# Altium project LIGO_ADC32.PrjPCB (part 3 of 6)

## Sheet FPGA_ARTIX7.SchDoc: FPGA
size C; Organization: Altium Limited; Address1: L3, 12a Rodborough Rd; Address2: Frenchs Forest; Address3: NSW; Address4: Australia 2086; DocumentNumber: 7; SheetNumber: 15; SheetTotal: 17
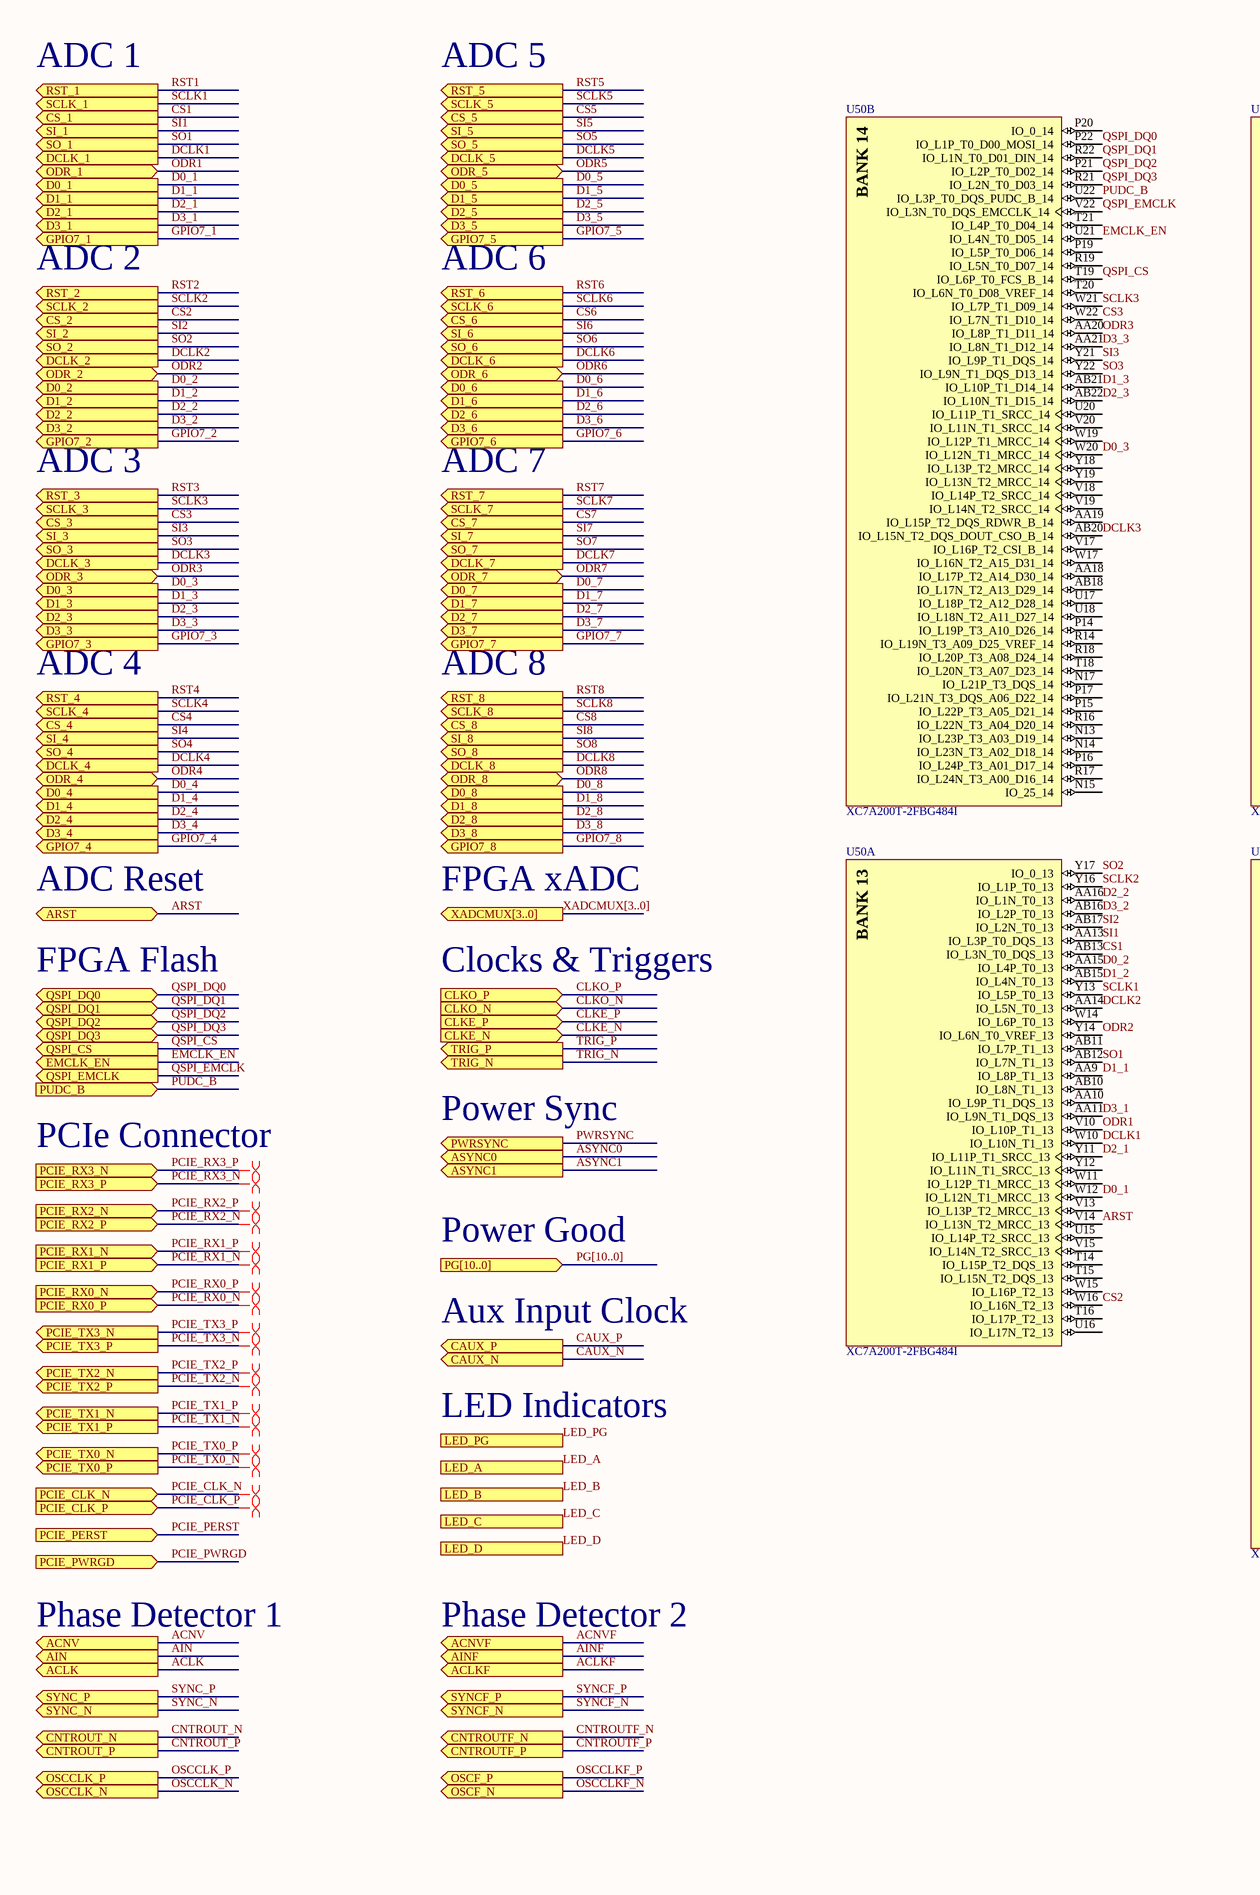
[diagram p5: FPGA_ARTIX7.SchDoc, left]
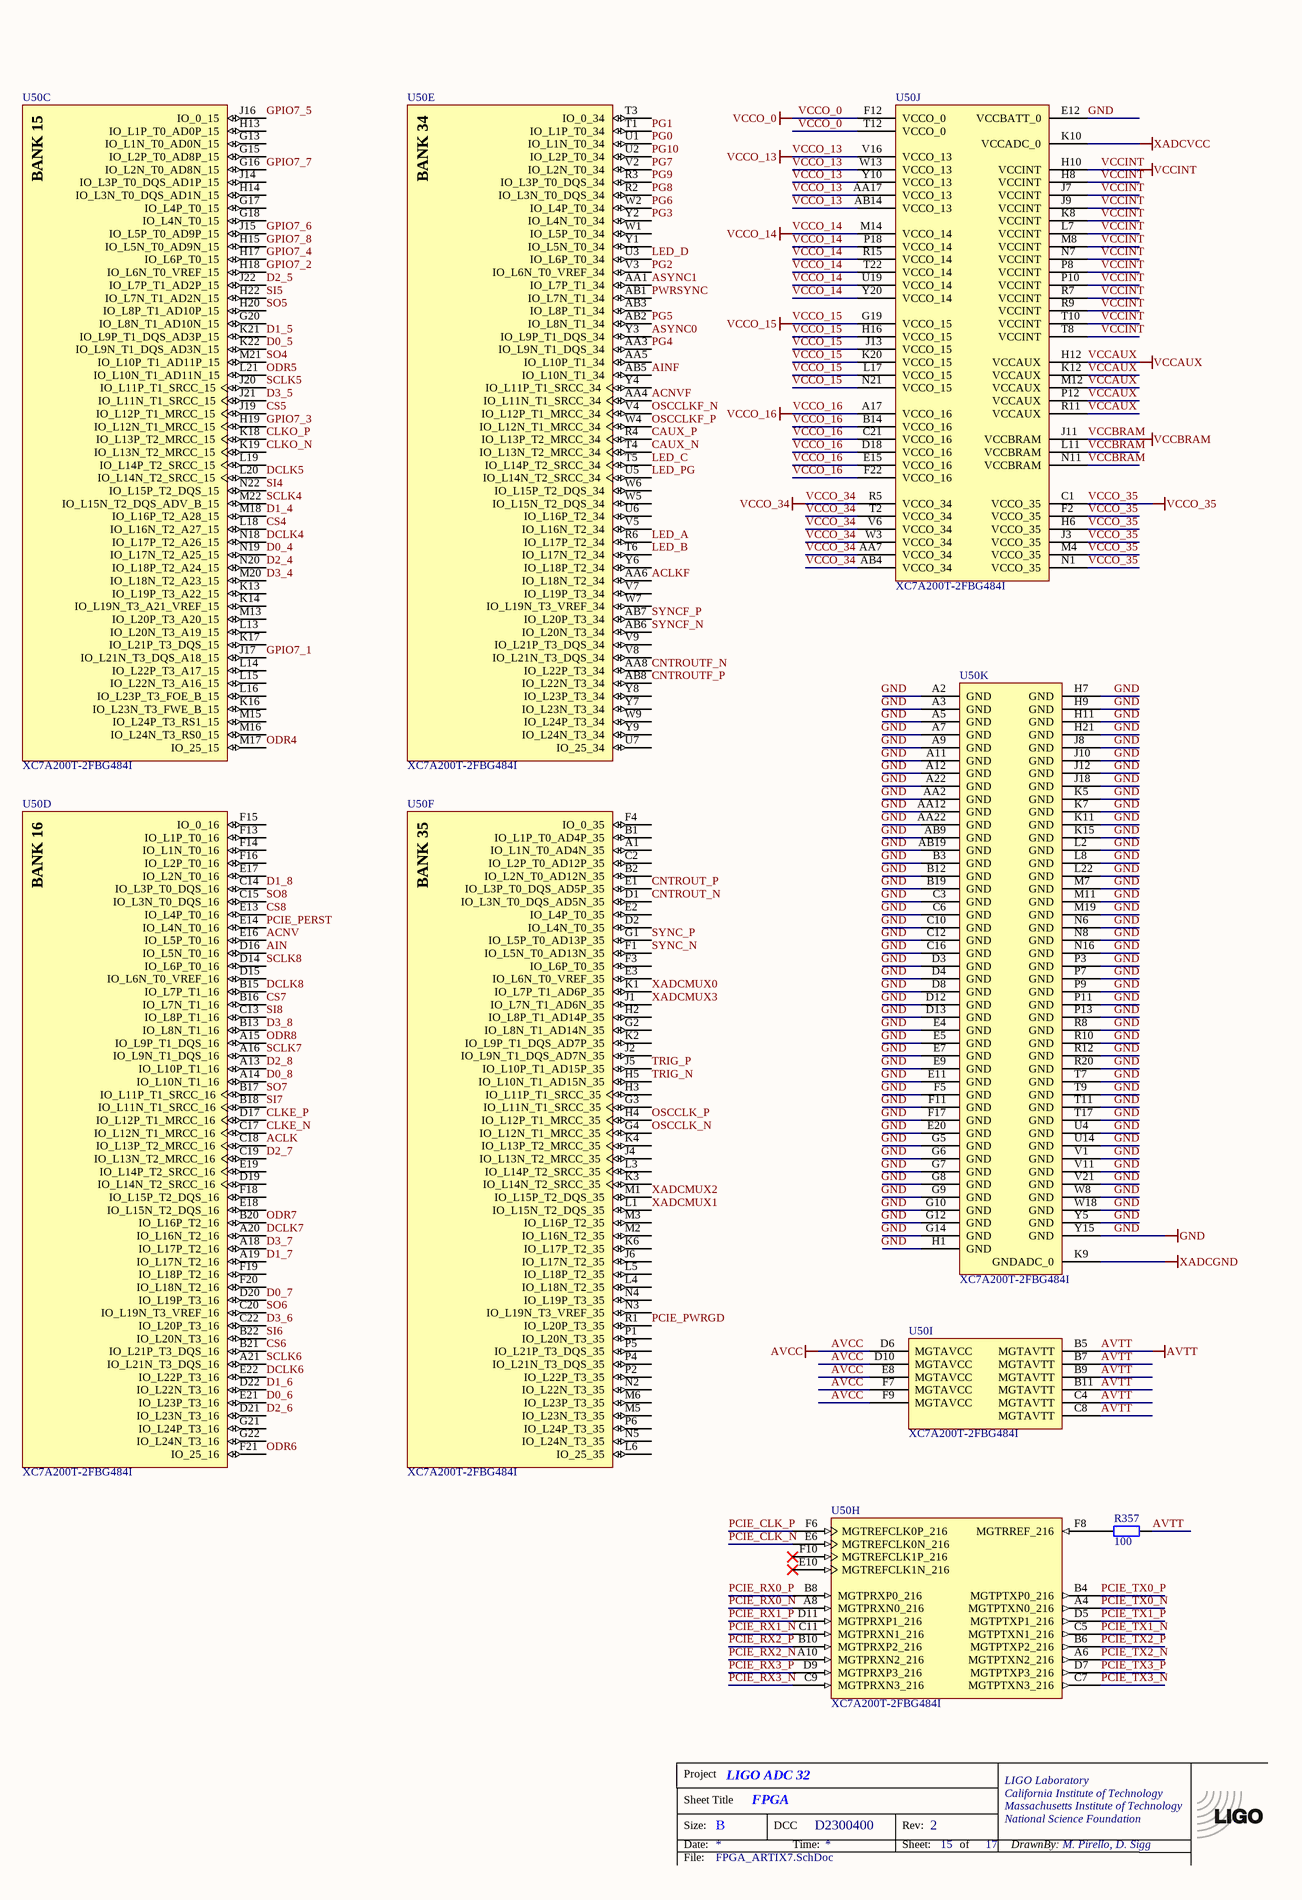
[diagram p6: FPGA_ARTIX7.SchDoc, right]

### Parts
(Parts that share a designator on the sheet are numbered #1, #2 ... from top to bottom, then left to right.)
*?#4  TitleBlock  (value not drawn)  (graphical)
R357  100  [CR1005-0402]
U50  XC7A200T-2FBG484I  [FBG484]  (parts A,B,C,D,E,F,H,I,J,K of 11)

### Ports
ACLK (out), ACLKF (out), ACNV (out), ACNVF (out), AIN (out), AINF (out), ARST (bidir), ASYNC0 (out), ASYNC1 (out), CAUX_N (out), CAUX_P (out), CLKE_N (in), CLKE_P (in), CLKO_N (in), CLKO_P (in), CNTROUT_N (out), CNTROUT_P (out), CNTROUTF_N (out), CNTROUTF_P (out), CS_1 (out), CS_2 (out), CS_3 (out), CS_4 (out), CS_5 (out), CS_6 (out), CS_7 (out), CS_8 (out), D0_1 (out), D0_2 (out), D0_3 (out), D0_4 (out), D0_5 (out), D0_6 (out), D0_7 (out), D0_8 (out), D1_1 (out), D1_2 (out), D1_3 (out), D1_4 (out), D1_5 (out), D1_6 (out), D1_7 (out), D1_8 (out), D2_1 (out), D2_2 (out), D2_3 (out), D2_4 (out), D2_5 (out), D2_6 (out), D2_7 (out), D2_8 (out), D3_1 (out), D3_2 (out), D3_3 (out), D3_4 (out), D3_5 (out), D3_6 (out), D3_7 (out), D3_8 (out), DCLK_1 (out), DCLK_2 (out), DCLK_3 (out), DCLK_4 (out), DCLK_5 (out), DCLK_6 (out), DCLK_7 (out), DCLK_8 (out), EMCLK_EN (out), GPIO7_1 (out), GPIO7_2 (out), GPIO7_3 (out), GPIO7_4 (out), GPIO7_5 (out), GPIO7_6 (out), GPIO7_7 (out), GPIO7_8 (out), LED_A (out), LED_B (out), LED_C (out), LED_D (out), LED_PG (out), ODR_1 (bidir), ODR_2 (bidir), ODR_3 (bidir), ODR_4 (bidir), ODR_5 (bidir), ODR_6 (bidir), ODR_7 (bidir), ODR_8 (bidir), OSCCLK_N (out), OSCCLK_P (out), OSCF_N (out), OSCF_P (out), PCIE_CLK_N (in), PCIE_CLK_P (in), PCIE_PERST (in), PCIE_PWRGD (in), PCIE_RX0_N (in), PCIE_RX0_P (in), PCIE_RX1_N (in), PCIE_RX1_P (in), PCIE_RX2_N (in), PCIE_RX2_P (in), PCIE_RX3_N (in), PCIE_RX3_P (in), PCIE_TX0_N (out), PCIE_TX0_P (out), PCIE_TX1_N (out), PCIE_TX1_P (out), PCIE_TX2_N (out), PCIE_TX2_P (out), PCIE_TX3_N (out), PCIE_TX3_P (out), PG[10..0] (in), PUDC_B (in), PWRSYNC (out), QSPI_CS (out), QSPI_DQ0 (bidir), QSPI_DQ1 (bidir), QSPI_DQ2 (bidir), QSPI_DQ3 (bidir), QSPI_EMCLK (out), RST_1 (out), RST_2 (out), RST_3 (out), RST_4 (out), RST_5 (out), RST_6 (out), RST_7 (out), RST_8 (out), SCLK_1 (out), SCLK_2 (out), SCLK_3 (out), SCLK_4 (out), SCLK_5 (out), SCLK_6 (out), SCLK_7 (out), SCLK_8 (out), SI_1 (out), SI_2 (out), SI_3 (out), SI_4 (out), SI_5 (out), SI_6 (out), SI_7 (out), SI_8 (out), SO_1 (out), SO_2 (out), SO_3 (out), SO_4 (out), SO_5 (out), SO_6 (out), SO_7 (out), SO_8 (out), SYNC_N (out), SYNC_P (out), SYNCF_N (out), SYNCF_P (out), TRIG_N (out), TRIG_P (out), XADCMUX[3..0] (out)

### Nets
AVCC: U50.D6(MGTAVCC) U50.D10(MGTAVCC) U50.E8(MGTAVCC) U50.F7(MGTAVCC) U50.F9(MGTAVCC)
AVTT: R357.2 U50.B5(MGTAVTT) U50.B7(MGTAVTT) U50.B9(MGTAVTT) U50.B11(MGTAVTT) U50.C4(MGTAVTT) U50.C8(MGTAVTT)
GND: U50.A2(GND) U50.A3(GND) U50.A5(GND) U50.A7(GND) U50.A9(GND) U50.A11(GND) U50.A12(GND) U50.A22(GND) U50.AA2(GND) U50.AA12(GND) U50.AA22(GND) U50.AB9(GND) U50.AB19(GND) U50.B3(GND) U50.B12(GND) U50.B19(GND) U50.C3(GND) U50.C6(GND) U50.C10(GND) U50.C12(GND) U50.C16(GND) U50.D3(GND) U50.D4(GND) U50.D8(GND) U50.D12(GND) U50.D13(GND) U50.E4(GND) U50.E5(GND) U50.E7(GND) U50.E9(GND) U50.E11(GND) U50.E12(VCCBATT_0) U50.E20(GND) U50.F5(GND) U50.F11(GND) U50.F17(GND) U50.G5(GND) U50.G6(GND) U50.G7(GND) U50.G8(GND) U50.G9(GND) U50.G10(GND) U50.G12(GND) U50.G14(GND) U50.H1(GND) U50.H7(GND) U50.H9(GND) U50.H11(GND) U50.H21(GND) U50.J8(GND) U50.J10(GND) U50.J12(GND) U50.J18(GND) U50.K5(GND) U50.K7(GND) U50.K11(GND) U50.K15(GND) U50.L2(GND) U50.L8(GND) U50.L22(GND) U50.M7(GND) U50.M11(GND) U50.M19(GND) U50.N6(GND) U50.N8(GND) U50.N16(GND) U50.P3(GND) U50.P7(GND) U50.P9(GND) U50.P11(GND) U50.P13(GND) U50.R8(GND) U50.R10(GND) U50.R12(GND) U50.R20(GND) U50.T7(GND) U50.T9(GND) U50.T11(GND) U50.T17(GND) U50.U4(GND) U50.U14(GND) U50.V1(GND) U50.V11(GND) U50.V21(GND) U50.W8(GND) U50.W18(GND) U50.Y5(GND) U50.Y15(GND)
VCCAUX: U50.A17(VCCO_16) U50.AA17(VCCO_13) U50.AB14(VCCO_13) U50.B14(VCCO_16) U50.C21(VCCO_16) U50.D18(VCCO_16) U50.E15(VCCO_16) U50.F12(VCCO_0) U50.F22(VCCO_16) U50.G19(VCCO_15) U50.H12(VCCAUX) U50.H16(VCCO_15) U50.J13(VCCO_15) U50.K12(VCCAUX) U50.K20(VCCO_15) U50.L17(VCCO_15) U50.M12(VCCAUX) U50.M14(VCCO_14) U50.N21(VCCO_15) U50.P12(VCCAUX) U50.P18(VCCO_14) U50.R11(VCCAUX) U50.R15(VCCO_14) U50.T12(VCCO_0) U50.T22(VCCO_14) U50.U19(VCCO_14) U50.V16(VCCO_13) U50.W13(VCCO_13) U50.Y10(VCCO_13) U50.Y20(VCCO_14)  [also labelled VCCO_0, VCCO_13, VCCO_14, VCCO_15, VCCO_16]  [project net VCC1V8]
VCCBRAM: U50.H8(VCCINT) U50.H10(VCCINT) U50.J7(VCCINT) U50.J9(VCCINT) U50.J11(VCCBRAM) U50.K8(VCCINT) U50.L7(VCCINT) U50.L11(VCCBRAM) U50.M8(VCCINT) U50.N7(VCCINT) U50.N11(VCCBRAM) U50.P8(VCCINT) U50.P10(VCCINT) U50.R7(VCCINT) U50.R9(VCCINT) U50.T8(VCCINT) U50.T10(VCCINT)  [also labelled VCCINT]  [project net VCC1V0]
VCCO_34: U50.AA7(VCCO_34) U50.AB4(VCCO_34) U50.C1(VCCO_35) U50.F2(VCCO_35) U50.H6(VCCO_35) U50.J3(VCCO_35) U50.M4(VCCO_35) U50.N1(VCCO_35) U50.R5(VCCO_34) U50.T2(VCCO_34) U50.V6(VCCO_34) U50.W3(VCCO_34)  [also labelled VCCO_35]  [project net VCC2V5]
XADCGND: U50.K9(GNDADC_0)
XADCVCC: U50.K10(VCCADC_0)
ACLK: U50.C18(IO_L13P_T2_MRCC_16) ; port ACLK  [project net CLOCK.ACLK]
ACLKF: U50.AA6(IO_L18N_T2_34) ; port ACLKF  [project net ACLK.ACLKF]
ACNV: U50.E16(IO_L5P_T0_16) ; port ACNV  [project net CLOCK.ACNV]
ACNVF: U50.AA4(IO_L11N_T1_SRCC_34) ; port ACNVF  [project net ACLK.ACNVF]
AIN: U50.D16(IO_L5N_T0_16) ; port AIN  [project net CLOCK.AIN]
AINF: U50.AB5(IO_L10N_T1_34) ; port AINF  [project net ACLK.AINF]
ARST: U50.V14(IO_L13N_T2_MRCC_13) ; port RST_1, port RST_2, port RST_3, port RST_4, port RST_5, port RST_6, port RST_7, port RST_8, port ARST  [also labelled RST1, RST2, RST3, RST4, RST5, RST6, RST7, RST8]  [project net ADC.RST]
ASYNC0: U50.Y3(IO_L9P_T1_DQS_34) ; port ASYNC0  [project net APWR1.SYNC_DIFF]
ASYNC1: U50.AA1(IO_L7P_T1_34) ; port ASYNC1  [project net APWR2.SYNC_DUAL]
CAUX_N: U50.T4(IO_L13N_T2_MRCC_34) ; port CAUX_N  [project net EXTCLK.CAUX_N]
CAUX_P: U50.R4(IO_L13P_T2_MRCC_34) ; port CAUX_P  [project net EXTCLK.CAUX_P]
CLKE_N: U50.C17(IO_L12N_T1_MRCC_16) ; port CLKE_N
CLKE_P: U50.D17(IO_L12P_T1_MRCC_16) ; port CLKE_P
CLKO_N: U50.K19(IO_L13N_T2_MRCC_15) ; port CLKO_N
CLKO_P: U50.K18(IO_L13P_T2_MRCC_15) ; port CLKO_P
CNTROUT_N: U50.D1(IO_L3N_T0_DQS_AD5N_35) ; port CNTROUT_N  [project net CLOCK.CNTROUT_N]
CNTROUT_P: U50.E1(IO_L3P_T0_DQS_AD5P_35) ; port CNTROUT_P  [project net CLOCK.CNTROUT_P]
CNTROUTF_N: U50.AA8(IO_L22P_T3_34) ; port CNTROUTF_N  [project net ACLK.CNTROUTF_N]
CNTROUTF_P: U50.AB8(IO_L22N_T3_34) ; port CNTROUTF_P  [project net ACLK.CNTROUTF_P]
CS1: U50.AB13(IO_L3N_T0_DQS_13) ; port CS_1  [project net ADC.CS]
CS2: U50.W16(IO_L16N_T2_13) ; port CS_2  [project net ADC.CS]
CS3: U50.W22(IO_L7N_T1_D10_14) ; port CS_3  [project net ADC.CS]
CS4: U50.L18(IO_L16N_T2_A27_15) ; port CS_4  [project net ADC.CS]
CS5: U50.J19(IO_L12P_T1_MRCC_15) ; port CS_5  [project net ADC.CS]
CS6: U50.B21(IO_L21P_T3_DQS_16) ; port CS_6  [project net ADC.CS]
CS7: U50.B16(IO_L7N_T1_16) ; port CS_7  [project net ADC.CS]
CS8: U50.E13(IO_L4P_T0_16) ; port CS_8  [project net ADC.CS]
D0_1: U50.W12(IO_L12N_T1_MRCC_13) ; port D0_1  [project net ADC.D0]
D0_2: U50.AA15(IO_L4P_T0_13) ; port D0_2  [project net ADC.D0]
D0_3: U50.W20(IO_L12N_T1_MRCC_14) ; port D0_3  [project net ADC.D0]
D0_4: U50.N19(IO_L17N_T2_A25_15) ; port D0_4  [project net ADC.D0]
D0_5: U50.K22(IO_L9N_T1_DQS_AD3N_15) ; port D0_5  [project net ADC.D0]
D0_6: U50.E21(IO_L23P_T3_16) ; port D0_6  [project net ADC.D0]
D0_7: U50.D20(IO_L19P_T3_16) ; port D0_7  [project net ADC.D0]
D0_8: U50.A14(IO_L10N_T1_16) ; port D0_8  [project net ADC.D0]
D1_1: U50.AA9(IO_L8P_T1_13) ; port D1_1  [project net ADC.D1]
D1_2: U50.AB15(IO_L4N_T0_13) ; port D1_2  [project net ADC.D1]
D1_3: U50.AB21(IO_L10P_T1_D14_14) ; port D1_3  [project net ADC.D1]
D1_4: U50.M18(IO_L16P_T2_A28_15) ; port D1_4  [project net ADC.D1]
D1_5: U50.K21(IO_L9P_T1_DQS_AD3P_15) ; port D1_5  [project net ADC.D1]
D1_6: U50.D22(IO_L22N_T3_16) ; port D1_6  [project net ADC.D1]
D1_7: U50.A19(IO_L17N_T2_16) ; port D1_7  [project net ADC.D1]
D1_8: U50.C14(IO_L3P_T0_DQS_16) ; port D1_8  [project net ADC.D1]
D2_1: U50.Y11(IO_L11P_T1_SRCC_13) ; port D2_1  [project net ADC.D2]
D2_2: U50.AA16(IO_L1N_T0_13) ; port D2_2  [project net ADC.D2]
D2_3: U50.AB22(IO_L10N_T1_D15_14) ; port D2_3  [project net ADC.D2]
D2_4: U50.N20(IO_L18P_T2_A24_15) ; port D2_4  [project net ADC.D2]
D2_5: U50.J22(IO_L7P_T1_AD2P_15) ; port D2_5  [project net ADC.D2]
D2_6: U50.D21(IO_L23N_T3_16) ; port D2_6  [project net ADC.D2]
D2_7: U50.C19(IO_L13N_T2_MRCC_16) ; port D2_7  [project net ADC.D2]
D2_8: U50.A13(IO_L10P_T1_16) ; port D2_8  [project net ADC.D2]
D3_1: U50.AA11(IO_L9N_T1_DQS_13) ; port D3_1  [project net ADC.D3]
D3_2: U50.AB16(IO_L2P_T0_13) ; port D3_2  [project net ADC.D3]
D3_3: U50.AA21(IO_L8N_T1_D12_14) ; port D3_3  [project net ADC.D3]
D3_4: U50.M20(IO_L18N_T2_A23_15) ; port D3_4  [project net ADC.D3]
D3_5: U50.J21(IO_L11N_T1_SRCC_15) ; port D3_5  [project net ADC.D3]
D3_6: U50.C22(IO_L20P_T3_16) ; port D3_6  [project net ADC.D3]
D3_7: U50.A18(IO_L17P_T2_16) ; port D3_7  [project net ADC.D3]
D3_8: U50.B13(IO_L8N_T1_16) ; port D3_8  [project net ADC.D3]
DCLK1: U50.W10(IO_L10N_T1_13) ; port DCLK_1  [project net ADC.DCLK]
DCLK2: U50.AA14(IO_L5N_T0_13) ; port DCLK_2  [project net ADC.DCLK]
DCLK3: U50.AB20(IO_L15N_T2_DQS_DOUT_CSO_B_14) ; port DCLK_3  [project net ADC.DCLK]
DCLK4: U50.N18(IO_L17P_T2_A26_15) ; port DCLK_4  [project net ADC.DCLK]
DCLK5: U50.L20(IO_L14N_T2_SRCC_15) ; port DCLK_5  [project net ADC.DCLK]
DCLK6: U50.E22(IO_L22P_T3_16) ; port DCLK_6  [project net ADC.DCLK]
DCLK7: U50.A20(IO_L16N_T2_16) ; port DCLK_7  [project net ADC.DCLK]
DCLK8: U50.B15(IO_L7P_T1_16) ; port DCLK_8  [project net ADC.DCLK]
EMCLK_EN: U50.U21(IO_L4N_T0_D05_14) ; port EMCLK_EN  [project net SQSPI.EMCLK_EN]
GPIO7_1: U50.J17(IO_L21N_T3_DQS_A18_15) ; port GPIO7_1  [project net ADC.GPIO7]
GPIO7_2: U50.H18(IO_L6N_T0_VREF_15) ; port GPIO7_2  [project net ADC.GPIO7]
GPIO7_3: U50.H19(IO_L12N_T1_MRCC_15) ; port GPIO7_3  [project net ADC.GPIO7]
GPIO7_4: U50.H17(IO_L6P_T0_15) ; port GPIO7_4  [project net ADC.GPIO7]
GPIO7_5: U50.J16(IO_0_15) ; port GPIO7_5  [project net ADC.GPIO7]
GPIO7_6: U50.J15(IO_L5P_T0_AD9P_15) ; port GPIO7_6  [project net ADC.GPIO7]
GPIO7_7: U50.G16(IO_L2N_T0_AD8N_15) ; port GPIO7_7  [project net ADC.GPIO7]
GPIO7_8: U50.H15(IO_L5N_T0_AD9N_15) ; port GPIO7_8  [project net ADC.GPIO7]
LED_A: U50.R6(IO_L17P_T2_34) ; port LED_A
LED_B: U50.T6(IO_L17N_T2_34) ; port LED_B
LED_C: U50.T5(IO_L14P_T2_SRCC_34) ; port LED_C
LED_D: U50.U3(IO_L6P_T0_34) ; port LED_D
LED_PG: U50.U5(IO_L14N_T2_SRCC_34) ; port LED_PG
ODR1: U50.V10(IO_L10P_T1_13) ; port ODR_1  [project net ADC.ODR]
ODR2: U50.Y14(IO_L6N_T0_VREF_13) ; port ODR_2  [project net ADC.ODR]
ODR3: U50.AA20(IO_L8P_T1_D11_14) ; port ODR_3  [project net ADC.ODR]
ODR4: U50.M17(IO_25_15) ; port ODR_4  [project net ADC.ODR]
ODR5: U50.L21(IO_L10N_T1_AD11N_15) ; port ODR_5  [project net ADC.ODR]
ODR6: U50.F21(IO_25_16) ; port ODR_6  [project net ADC.ODR]
ODR7: U50.B20(IO_L16P_T2_16) ; port ODR_7  [project net ADC.ODR]
ODR8: U50.A15(IO_L9P_T1_DQS_16) ; port ODR_8  [project net ADC.ODR]
OSCCLK_N: U50.G4(IO_L12N_T1_MRCC_35) ; port OSCCLK_N  [project net CLOCK.OSCCLK_N]
OSCCLK_P: U50.H4(IO_L12P_T1_MRCC_35) ; port OSCCLK_P  [project net CLOCK.OSCCLK_P]
OSCCLKF_N: U50.V4(IO_L12P_T1_MRCC_34) ; port OSCF_N  [project net ACLK.OSCCLKF_N]
OSCCLKF_P: U50.W4(IO_L12N_T1_MRCC_34) ; port OSCF_P  [project net ACLK.OSCCLKF_P]
PCIE_CLK_N: U50.E6(MGTREFCLK0N_216) ; port PCIE_CLK_N  [project net PCIE.PCIE_CLK_N]
PCIE_CLK_P: U50.F6(MGTREFCLK0P_216) ; port PCIE_CLK_P  [project net PCIE.PCIE_CLK_P]
PCIE_PERST: U50.E14(IO_L4N_T0_16) ; port PCIE_PERST  [project net PCIE.PCIE_PERST]
PCIE_PWRGD: U50.R1(IO_L20P_T3_35) ; port PCIE_PWRGD  [project net PCIE.PCIE_PWRGD]
PCIE_RX0_N: U50.A8(MGTPRXN0_216) ; port PCIE_RX0_P  [project net PCIE.PCIE_RX0_P]
PCIE_RX0_P: U50.B8(MGTPRXP0_216) ; port PCIE_RX0_N  [project net PCIE.PCIE_RX0_N]
PCIE_RX1_N: U50.C11(MGTPRXN1_216) ; port PCIE_RX1_P  [project net PCIE.PCIE_RX1_P]
PCIE_RX1_P: U50.D11(MGTPRXP1_216) ; port PCIE_RX1_N  [project net PCIE.PCIE_RX1_N]
PCIE_RX2_N: U50.A10(MGTPRXN2_216) ; port PCIE_RX2_P  [project net PCIE.PCIE_RX2_P]
PCIE_RX2_P: U50.B10(MGTPRXP2_216) ; port PCIE_RX2_N  [project net PCIE.PCIE_RX2_N]
PCIE_RX3_N: U50.C9(MGTPRXN3_216) ; port PCIE_RX3_P  [project net PCIE.PCIE_RX3_P]
PCIE_RX3_P: U50.D9(MGTPRXP3_216) ; port PCIE_RX3_N  [project net PCIE.PCIE_RX3_N]
PCIE_TX0_N: U50.A4(MGTPTXN0_216) ; port PCIE_TX0_P  [project net PCIE.PCIE_TX0_P]
PCIE_TX0_P: U50.B4(MGTPTXP0_216) ; port PCIE_TX0_N  [project net PCIE.PCIE_TX0_N]
PCIE_TX1_N: U50.C5(MGTPTXN1_216) ; port PCIE_TX1_P  [project net PCIE.PCIE_TX1_P]
PCIE_TX1_P: U50.D5(MGTPTXP1_216) ; port PCIE_TX1_N  [project net PCIE.PCIE_TX1_N]
PCIE_TX2_N: U50.A6(MGTPTXN2_216) ; port PCIE_TX2_P  [project net PCIE.PCIE_TX2_P]
PCIE_TX2_P: U50.B6(MGTPTXP2_216) ; port PCIE_TX2_N  [project net PCIE.PCIE_TX2_N]
PCIE_TX3_N: U50.C7(MGTPTXN3_216) ; port PCIE_TX3_P  [project net PCIE.PCIE_TX3_P]
PCIE_TX3_P: U50.D7(MGTPTXP3_216) ; port PCIE_TX3_N  [project net PCIE.PCIE_TX3_N]
PG0: U50.U1(IO_L1N_T0_34)
PG1: U50.T1(IO_L1P_T0_34)
PG2: U50.V3(IO_L6N_T0_VREF_34)
PG3: U50.Y2(IO_L4N_T0_34)
PG4: U50.AA3(IO_L9N_T1_DQS_34)
PG5: U50.AB2(IO_L8N_T1_34)
PG6: U50.W2(IO_L4P_T0_34)
PG7: U50.V2(IO_L2N_T0_34)
PG8: U50.R2(IO_L3N_T0_DQS_34)
PG9: U50.R3(IO_L3P_T0_DQS_34)
PG10: U50.U2(IO_L2P_T0_34)
PUDC_B: U50.U22(IO_L3P_T0_DQS_PUDC_B_14) ; port PUDC_B  [project net SQSPI.PUDC_B]
PWRSYNC: U50.AB1(IO_L7N_T1_34) ; port PWRSYNC  [project net POWER.PWRSYNC]
QSPI_CS: U50.T19(IO_L6P_T0_FCS_B_14) ; port QSPI_CS  [project net SQSPI.QSPI_CS]
QSPI_DQ0: U50.P22(IO_L1P_T0_D00_MOSI_14) ; port QSPI_DQ0  [project net SQSPI.QSPI_DQ0]
QSPI_DQ1: U50.R22(IO_L1N_T0_D01_DIN_14) ; port QSPI_DQ1  [project net SQSPI.QSPI_DQ1]
QSPI_DQ2: U50.P21(IO_L2P_T0_D02_14) ; port QSPI_DQ2  [project net SQSPI.QSPI_DQ2]
QSPI_DQ3: U50.R21(IO_L2N_T0_D03_14) ; port QSPI_DQ3  [project net SQSPI.QSPI_DQ3]
QSPI_EMCLK: U50.V22(IO_L3N_T0_DQS_EMCCLK_14) ; port QSPI_EMCLK  [project net SQSPI.QSPI_EMCLK]
SCLK1: U50.Y13(IO_L5P_T0_13) ; port SCLK_1  [project net ADC.SCLK]
SCLK2: U50.Y16(IO_L1P_T0_13) ; port SCLK_2  [project net ADC.SCLK]
SCLK3: U50.W21(IO_L7P_T1_D09_14) ; port SCLK_3  [project net ADC.SCLK]
SCLK4: U50.M22(IO_L15N_T2_DQS_ADV_B_15) ; port SCLK_4  [project net ADC.SCLK]
SCLK5: U50.J20(IO_L11P_T1_SRCC_15) ; port SCLK_5  [project net ADC.SCLK]
SCLK6: U50.A21(IO_L21N_T3_DQS_16) ; port SCLK_6  [project net ADC.SCLK]
SCLK7: U50.A16(IO_L9N_T1_DQS_16) ; port SCLK_7  [project net ADC.SCLK]
SCLK8: U50.D14(IO_L6P_T0_16) ; port SCLK_8  [project net ADC.SCLK]
SI1: U50.AA13(IO_L3P_T0_DQS_13) ; port SI_1  [project net ADC.SI]
SI2: U50.AB17(IO_L2N_T0_13) ; port SI_2  [project net ADC.SI]
SI3: U50.Y21(IO_L9P_T1_DQS_14) ; port SI_3  [project net ADC.SI]
SI4: U50.N22(IO_L15P_T2_DQS_15) ; port SI_4  [project net ADC.SI]
SI5: U50.H22(IO_L7N_T1_AD2N_15) ; port SI_5  [project net ADC.SI]
SI6: U50.B22(IO_L20N_T3_16) ; port SI_6  [project net ADC.SI]
SI7: U50.B18(IO_L11N_T1_SRCC_16) ; port SI_7  [project net ADC.SI]
SI8: U50.C13(IO_L8P_T1_16) ; port SI_8  [project net ADC.SI]
SO1: U50.AB12(IO_L7N_T1_13) ; port SO_1  [project net ADC.SO]
SO2: U50.Y17(IO_0_13) ; port SO_2  [project net ADC.SO]
SO3: U50.Y22(IO_L9N_T1_DQS_D13_14) ; port SO_3  [project net ADC.SO]
SO4: U50.M21(IO_L10P_T1_AD11P_15) ; port SO_4  [project net ADC.SO]
SO5: U50.H20(IO_L8P_T1_AD10P_15) ; port SO_5  [project net ADC.SO]
SO6: U50.C20(IO_L19N_T3_VREF_16) ; port SO_6  [project net ADC.SO]
SO7: U50.B17(IO_L11P_T1_SRCC_16) ; port SO_7  [project net ADC.SO]
SO8: U50.C15(IO_L3N_T0_DQS_16) ; port SO_8  [project net ADC.SO]
SYNC_N: U50.F1(IO_L5N_T0_AD13N_35) ; port SYNC_N  [project net CLOCK.SYNC_N]
SYNC_P: U50.G1(IO_L5P_T0_AD13P_35) ; port SYNC_P  [project net CLOCK.SYNC_P]
SYNCF_N: U50.AB6(IO_L20N_T3_34) ; port SYNCF_N  [project net ACLK.SYNCF_N]
SYNCF_P: U50.AB7(IO_L20P_T3_34) ; port SYNCF_P  [project net ACLK.SYNCF_P]
TRIG_N: U50.H5(IO_L10N_T1_AD15N_35) ; port TRIG_N  [project net EXT.TRIGout_N]
TRIG_P: U50.J5(IO_L10P_T1_AD15P_35) ; port TRIG_P  [project net EXT.TRIGout_P]
XADCMUX0: U50.K1(IO_L7P_T1_AD6P_35)  [project net XMUX0]
XADCMUX1: U50.L1(IO_L15N_T2_DQS_35)  [project net XMUX1]
XADCMUX2: U50.M1(IO_L15P_T2_DQS_35)  [project net XMUX2]
XADCMUX3: U50.J1(IO_L7N_T1_AD6N_35)  [project net XMUX3]
NetR357_1: R357.1 U50.F8(MGTRREF_216)

Not connected (* = marked no-connect by the designer): U50 A1(IO_L1N_T0_AD4N_35) AA5(IO_L10P_T1_34) AA10(IO_L9P_T1_DQS_13) AA18(IO_L17P_T2_A14_D30_14) AA19(IO_L15P_T2_DQS_RDWR_B_14) AB3(IO_L8P_T1_34) AB10(IO_L8N_T1_13) AB11(IO_L7P_T1_13) AB18(IO_L17N_T2_A13_D29_14) B1(IO_L1P_T0_AD4P_35) B2(IO_L2N_T0_AD12N_35) C2(IO_L2P_T0_AD12P_35) D2(IO_L4N_T0_35) D15(IO_L6N_T0_VREF_16) D19(IO_L14N_T2_SRCC_16) E2(IO_L4P_T0_35) E3(IO_L6N_T0_VREF_35) E10(MGTREFCLK1N_216)* E17(IO_L2N_T0_16) E18(IO_L15N_T2_DQS_16) E19(IO_L14P_T2_SRCC_16) F3(IO_L6P_T0_35) F4(IO_0_35) F10(MGTREFCLK1P_216)* F13(IO_L1P_T0_16) F14(IO_L1N_T0_16) F15(IO_0_16) F16(IO_L2P_T0_16) F18(IO_L15P_T2_DQS_16) F19(IO_L18P_T2_16) F20(IO_L18N_T2_16) G2(IO_L8N_T1_AD14N_35) G3(IO_L11N_T1_SRCC_35) G13(IO_L1N_T0_AD0N_15) G15(IO_L2P_T0_AD8P_15) G17(IO_L4P_T0_15) G18(IO_L4N_T0_15) G20(IO_L8N_T1_AD10N_15) G21(IO_L24P_T3_16) G22(IO_L24N_T3_16) H2(IO_L8P_T1_AD14P_35) H3(IO_L11P_T1_SRCC_35) H13(IO_L1P_T0_AD0P_15) H14(IO_L3N_T0_DQS_AD1N_15) J2(IO_L9N_T1_DQS_AD7N_35) J4(IO_L13N_T2_MRCC_35) J6(IO_L17N_T2_35) J14(IO_L3P_T0_DQS_AD1P_15) K2(IO_L9P_T1_DQS_AD7P_35) K3(IO_L14N_T2_SRCC_35) K4(IO_L13P_T2_MRCC_35) K6(IO_L17P_T2_35) K13(IO_L19P_T3_A22_15) K14(IO_L19N_T3_A21_VREF_15) K16(IO_L23N_T3_FWE_B_15) K17(IO_L21P_T3_DQS_15) L3(IO_L14P_T2_SRCC_35) L4(IO_L18N_T2_35) L5(IO_L18P_T2_35) L6(IO_25_35) L13(IO_L20N_T3_A19_15) L14(IO_L22P_T3_A17_15) L15(IO_L22N_T3_A16_15) L16(IO_L23P_T3_FOE_B_15) L19(IO_L14P_T2_SRCC_15) M2(IO_L16N_T2_35) M3(IO_L16P_T2_35) M5(IO_L23N_T3_35) M6(IO_L23P_T3_35) M13(IO_L20P_T3_A20_15) M15(IO_L24P_T3_RS1_15) M16(IO_L24N_T3_RS0_15) N2(IO_L22N_T3_35) N3(IO_L19N_T3_VREF_35) N4(IO_L19P_T3_35) N5(IO_L24N_T3_35) N13(IO_L23P_T3_A03_D19_14) N14(IO_L23N_T3_A02_D18_14) N15(IO_25_14) N17(IO_L21P_T3_DQS_14) P1(IO_L20N_T3_35) P2(IO_L22P_T3_35) P4(IO_L21N_T3_DQS_35) P5(IO_L21P_T3_DQS_35) P6(IO_L24P_T3_35) P14(IO_L19P_T3_A10_D26_14) P15(IO_L22P_T3_A05_D21_14) P16(IO_L24P_T3_A01_D17_14) P17(IO_L21N_T3_DQS_A06_D22_14) P19(IO_L5P_T0_D06_14) P20(IO_0_14) R14(IO_L19N_T3_A09_D25_VREF_14) R16(IO_L22N_T3_A04_D20_14) R17(IO_L24N_T3_A00_D16_14) R18(IO_L20P_T3_A08_D24_14) R19(IO_L5N_T0_D07_14) T3(IO_0_34) T14(IO_L15P_T2_DQS_13) T15(IO_L15N_T2_DQS_13) T16(IO_L17P_T2_13) T18(IO_L20N_T3_A07_D23_14) T20(IO_L6N_T0_D08_VREF_14) T21(IO_L4P_T0_D04_14) U6(IO_L16P_T2_34) U7(IO_25_34) U15(IO_L14P_T2_SRCC_13) U16(IO_L17N_T2_13) U17(IO_L18P_T2_A12_D28_14) U18(IO_L18N_T2_A11_D27_14) U20(IO_L11P_T1_SRCC_14) V5(IO_L16N_T2_34) V7(IO_L19P_T3_34) V8(IO_L21N_T3_DQS_34) V9(IO_L21P_T3_DQS_34) V13(IO_L13P_T2_MRCC_13) V15(IO_L14N_T2_SRCC_13) V17(IO_L16P_T2_CSI_B_14) V18(IO_L14P_T2_SRCC_14) V19(IO_L14N_T2_SRCC_14) V20(IO_L11N_T1_SRCC_14) W1(IO_L5P_T0_34) W5(IO_L15N_T2_DQS_34) W6(IO_L15P_T2_DQS_34) W7(IO_L19N_T3_VREF_34) W9(IO_L24P_T3_34) W11(IO_L12P_T1_MRCC_13) W14(IO_L6P_T0_13) W15(IO_L16P_T2_13) W17(IO_L16N_T2_A15_D31_14) W19(IO_L12P_T1_MRCC_14) Y1(IO_L5N_T0_34) Y4(IO_L11P_T1_SRCC_34) Y6(IO_L18P_T2_34) Y7(IO_L23N_T3_34) Y8(IO_L23P_T3_34) Y9(IO_L24N_T3_34) Y12(IO_L11N_T1_SRCC_13) Y18(IO_L13P_T2_MRCC_14) Y19(IO_L13N_T2_MRCC_14)

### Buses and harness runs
bus PG[10..0] = port PG[10..0]
bus XADCMUX[3..0] = port XADCMUX[3..0]

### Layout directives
differential pair: PCIE.PCIE_CLK_N, PCIE.PCIE_CLK_P, PCIE.PCIE_RX0_N, PCIE.PCIE_RX0_P, PCIE.PCIE_RX1_N, PCIE.PCIE_RX1_P, PCIE.PCIE_RX2_N, PCIE.PCIE_RX2_P, PCIE.PCIE_RX3_N, PCIE.PCIE_RX3_P, PCIE.PCIE_TX0_N, PCIE.PCIE_TX0_P, PCIE.PCIE_TX1_N, PCIE.PCIE_TX1_P, PCIE.PCIE_TX2_N, PCIE.PCIE_TX2_P, PCIE.PCIE_TX3_N, PCIE.PCIE_TX3_P

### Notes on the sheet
- ADC 1
- ADC 5
- ADC 2
- ADC 6
- ADC 3
- ADC 7
- ADC 4
- ADC 8
- ADC Reset
- FPGA xADC
- FPGA Flash
- Clocks & Triggers
- PCIe Connector
- Power Sync
- Power Good
- Aux Input Clock
- LED Indicators
- Phase Detector 1
- Phase Detector 2

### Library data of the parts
R357 = ChipRes1: R0402 100; Part Number: TNPW0402100RBEED
U50 = CMP-0364-00012-3: Artix-7 FPGA, 285 User I/Os, 4 GTP, 484-Ball BGA, Speed Grade 2, Industrial Grade, Pb-Free; Part Number: XC7A200T-2FBG484C

## Sheet AD32_XADC.SchDoc: XADC
size B; DocumentNumber: 5; Revision: C; SheetNumber: 14; SheetTotal: 17; SPICEModelCacheGFFRXQKT: <root> / <DocumentId>GFFRXQKT</DocumentId> / <CacheFrame Number="0"> / <Model Name="op284f" Kind="CKT"> / <Text>* OP284F SPICE Macro-model              11/95 / Rev. B / *                                       ARG / ADSC / * / * Revision History: / * / *     Rev. B / * Changed the short-circuit output current limit from +/- 7.5mA / * to +/- 6.5mA to reflect final data sheet limits. / * / * Changed Vos spec to conform to final data sheet value of / * 125uV, up from 50uV. / * / * / * This version of the OP284 model simulates the worst-case / * parameters of the 'F' grade.  The worst-case parameters / * used correspond to those in the data sheet. / * / * Copyright 1993 by Analog Devices / * / * Refer to "README.DOC" file for License Statement. Use of this model / * indicates your acceptance of the terms and provisions in the License / * Statement. / * / * Node assignments / *                non-inverting input / *                ¦   inverting input / *                ¦   ¦   positive supply / *                ¦   ¦   ¦   negative supply / *                ¦   ¦   ¦   ¦   output / *                ¦   ¦   ¦   ¦   ¦ / .SUBCKT OP284F   1   2   99  50  45 / * / * INPUT STAGE / * / Q1   5    2    3    QIN 1 / Q2   6    11   3    QIN 1 / Q3   7    2    4    QIP 1 / Q4   8    11   4    QIP 1 / DC1  2    11   DC / DC2  11   2    DC / Q5   4    9    99   QIP 1 / Q6   9    9    99   QIP 1 / Q7   3    10   50   QIN 1 / Q8   10   10   50   QIN 1 / R1   99   5    4E3 / R2   99   6    4E3 / R3   7    50   4E3 / R4   8    50   4E3 / IREF 9    10   50.5E-6 / EOS  1    11   POLY(2) (22,98) (14,98) -125E-6 501.2E-3 1 / IOS  2    1    25E-9 / CIN  1    2    2E-12 / GN1  98   1    17 98 1E-3 / GN2  98   2    23 98 1E-3 / * / * VOLTAGE NOISE SOURCE WITH FLICKER NOISE / * / VN1  13   98   DC 2 / VN2  98   15   DC 2 / DN1  13   14   DEN / DN2  14   15   DEN / * / * CURRENT NOISE SOURCE WITH FLICKER NOISE / * / VN3  16   98   DC 2 / VN4  98   18   DC 2 / DN3  16   17   DIN / DN4  17   18   DIN / * / * 2ND CURRENT NOISE SOURCE WITH FLICKER NOISE / * / VN5  19   98   DC 2 / VN6  98   24   DC 2 / DN5  19   23   DIN / DN6  23   24   DIN / * / * GAIN STAGE / * / EREF 98   0    POLY(2) (99,0) (50,0) 0 0.5 0.5 / G1   98   20   POLY(2) (6,5) (8,7) 0 0.5E-3 0.5E-3 / R9   20   98   1E3 / * / * COMMON MODE STAGE WITH ZERO AT 5KHZ / * / ECM  98   21   POLY(2) (1,98) (2,98) 0 0.5 0.5 / R10  21   22   1 / R11  22   98   100E-6 / C4   21   22   31.756E-6 / * / * NEGATIVE ZERO AT 20MHZ / * / E1   27   98   20 98 1 / R17  27   28   1 / R18  28   98   1E-6 / C8   25   26   7.958E-9 / ENZ  25   98   27 28 1 / VNZ  26   98   DC 0 / FNZ  27   28   VNZ -1 / * / * POLE AT 40MHZ / * / G4   98   29   28 98 1E6 / R19  29   98   1 / C9   29   98   3.979E-9 / * / * POLE AT 40MHZ / * / G5   98   30   29 98 1 / R20  30   98   1 / C10  30   98   3.979E-9 / * / * OUTUT STAGE / * / ISY  99   50   0.526E-3 / GIN  50   31   POLY(1) (30,98) 0.862574E-6 511.855E-6 / RIN  31   50   2.75E6 / VB   99   32   0.7 / Q11  32   31   33   QON 1 / R21  33   34   4.5E3 / I1   34   50   50E-6 / R22  99   35   6E3 / Q12  36   36   35   QOP 1 / I2   36   50   50E-6 / R23  99   37   2.6E3 / R24  34   38   5E3 / Q13  39   36   37   QOP 1 / Q14  39   38   40   QON 1.5 / R25  40   50   40 / Q15  39   39   41   QON 1 / R26  41   42   1E3 / R27  99   43   220 / Q16  44   44   43   QOP 1.5 / Q17  44   39   42   QON 1 / R28  42   50   2E3 / VSCP 99   97   DC 0 / FSCP 46   99   VSCP 1 / RSCP 46   99   125 / Q20  44   46   99   QOP 1 / Q18  45   44   97   QOP 4.5 / Q19  45   34   51   QON 4.5 / VSCN 51   50   DC 0 / FSCN 50   47   VSCN 1 / RSCN 47   50   122 / Q21  34   47   50   QON 1 / CC2  31   45   20E-12 / CF1  31   34   15E-12 / CF2  31   42   15E-12 / CO1  34   45   15E-12 / CO2  42   45   5E-12 / D3   45   99   DX / D4   50   45   DX / .MODEL DC D(IS=130E-21) / .MODEL DX D() / .MODEL DEN D(RS=100 KF=12E-15 AF=1) / .MODEL DIN D(RS=5.358 KF=56E-15 AF=1) / .MODEL QIN NPN(BF=250 VA=200 IS=0.5E-16) / .MODEL QIP PNP(BF=60 VA=100 IS=0.5E-16) / .MODEL QON NPN(BF=200 VA=200 IS=0.5E-16 RC=140) / .MODEL QOP PNP(BF=200 VA=200 IS=0.5E-16 RC=210) / .ENDS</Text> / </Model> / </CacheFrame> / </root>
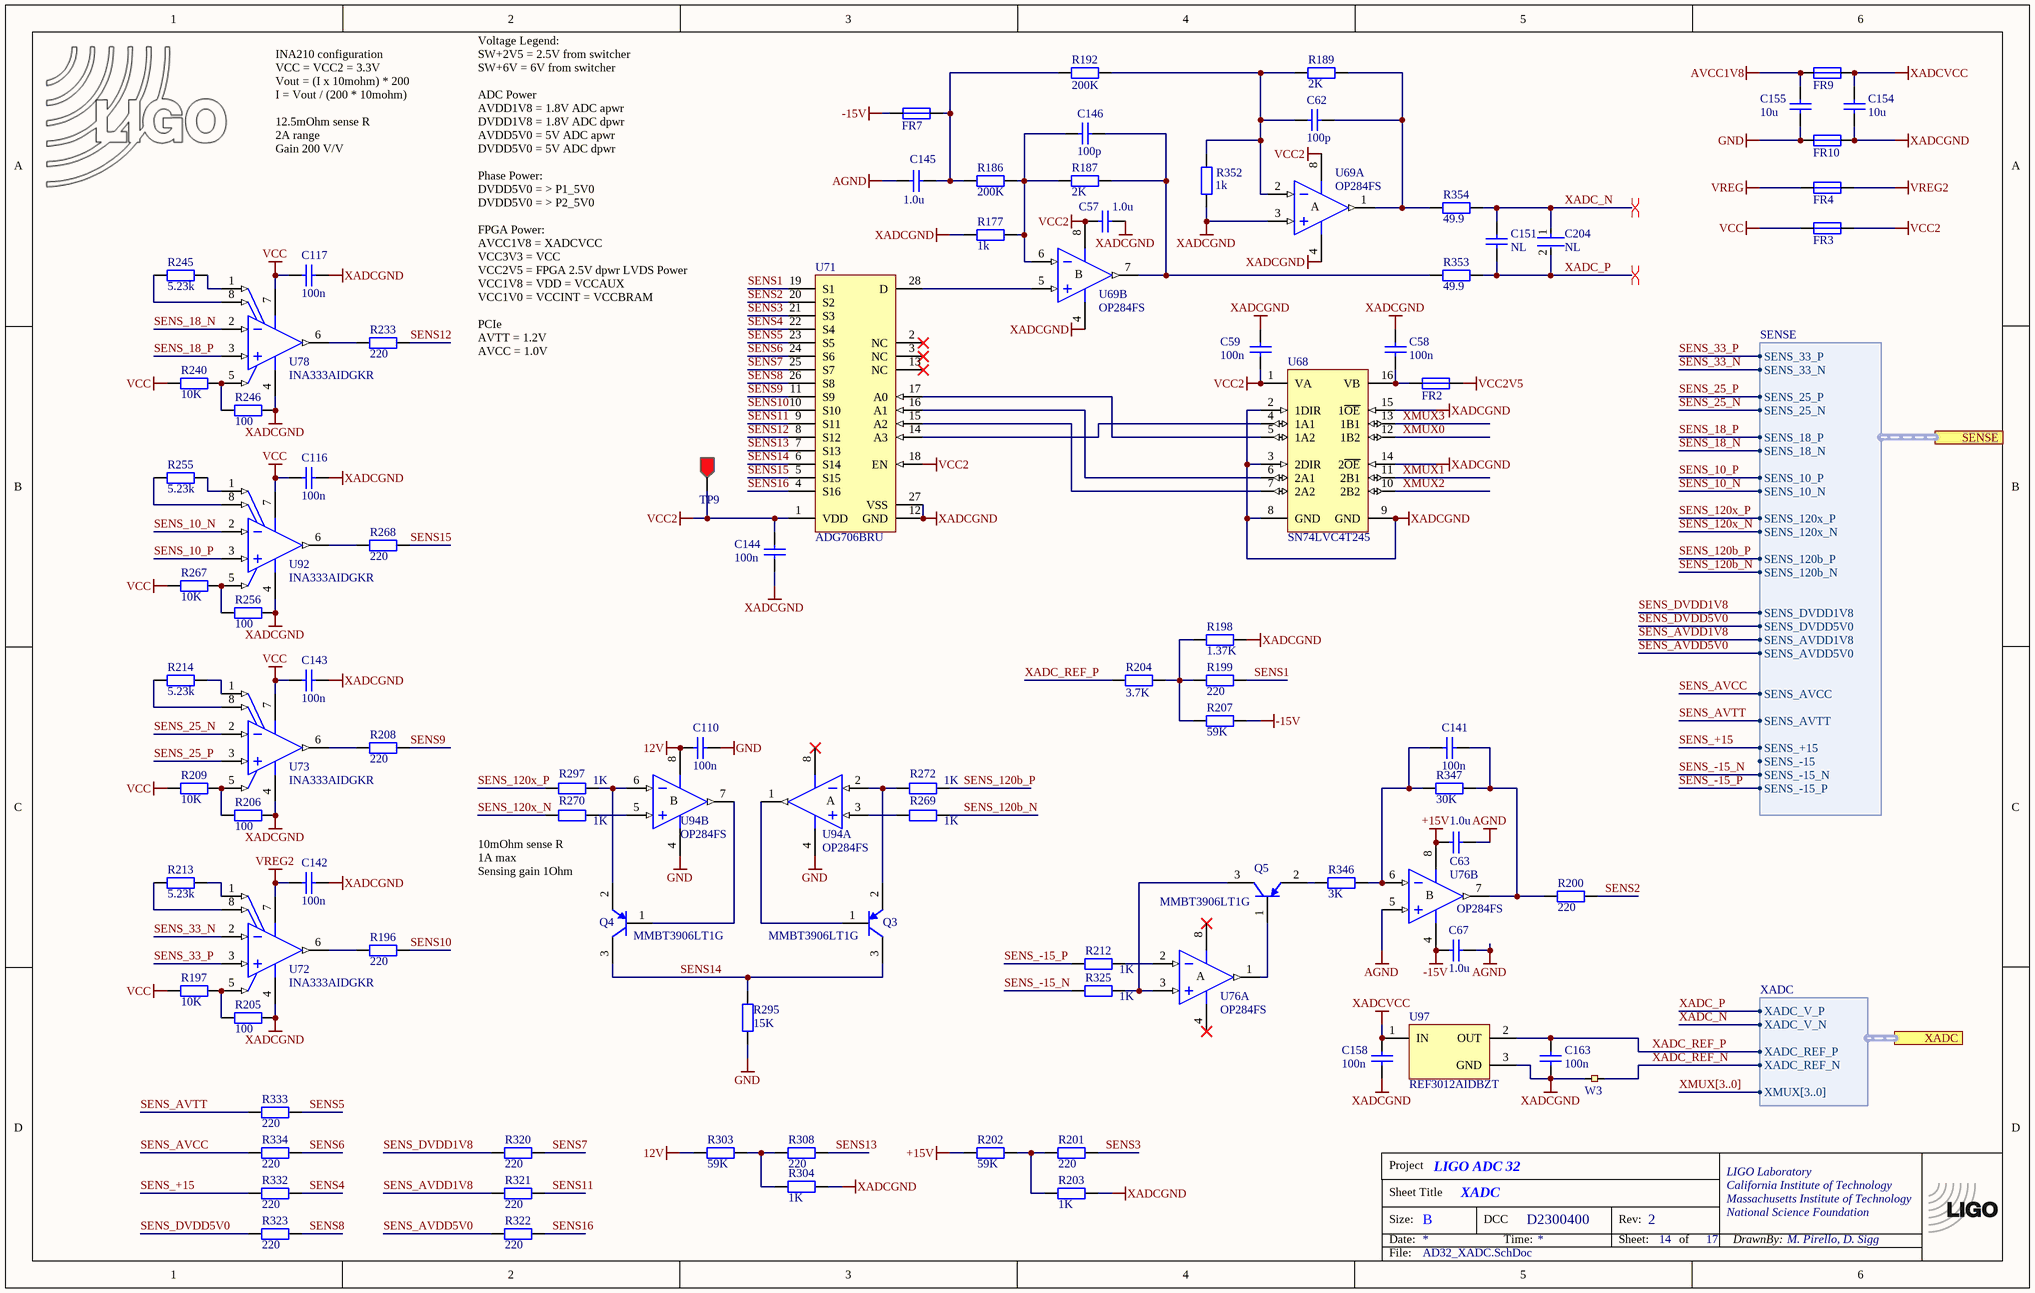
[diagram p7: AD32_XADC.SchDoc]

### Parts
(Parts that share a designator on the sheet are numbered #1, #2 ... from top to bottom, then left to right.)
*  TitleBlock  (value not drawn)  (graphical)
C57  1.0u  [CC1005-0402]
C58  100n  [CC1005-0402]
C59  100n  [CC1005-0402]
C62  100p  [CC1005-0402]
C63  1.0u  [CC1608-0603]
C67  1.0u  [CC1608-0603]
C110  100n  [CC1005-0402]
C116  100n  [CC1005-0402]
C117  100n  [CC1005-0402]
C141  100n  [CC1005-0402]
C142  100n  [CC1005-0402]
C143  100n  [CC1005-0402]
C144  100n  [CC1005-0402]
C145  1.0u  [CC1005-0402]
C146  100p  [CC1005-0402]
C151  NL  [CC1005-0402]
C154  10u  [CC2013-0805]
C155  10u  [CC2013-0805]
C158  100n  [CC1005-0402]
C163  100n  [CC1005-0402]
C204  NL  [FP-CL03-IPC_B]
FR2  BLM31PG121  [CC3216-1206]  (value not drawn)
FR3  BLM31PG121  [CC3216-1206]  (value not drawn)
FR4  BLM31PG121  [CC3216-1206]  (value not drawn)
FR7  BLM31PG121  [CC3216-1206]  (value not drawn)
FR9  BLM31PG121  [CC3216-1206]  (value not drawn)
FR10  BLM31PG121  [CC3216-1206]  (value not drawn)
LOGO4#1  LIGO logo  [LIGO_LOGO]  (value not drawn)  (graphical)
Q3  MMBT3906LT1G  [ONSC-SOT-23-3-318-08_V]
Q4  MMBT3906LT1G  [ONSC-SOT-23-3-318-08_V]
Q5  MMBT3906LT1G  [ONSC-SOT-23-3-318-08_V]
R177  1k  [CR1608-0603]
R186  200K  [CR1005-0402]
R187  2K  [CR1005-0402]
R189  2K  [CR1005-0402]
R192  200K  [CR1005-0402]
R196  220  [CR1608-0603]
R197  10K  [CR1608-0603]
R198  1.37K  [CR1608-0603]
R199  220  [CR1608-0603]
R200  220  [CR1608-0603]
R201  220  [CR1608-0603]
R202  59K  [CR1608-0603]
R203  1K  [CR1608-0603]
R204  3.7K  [CR1608-0603]
R205  100  [CR1005-0402]
R206  100  [CR1005-0402]
R207  59K  [CR1608-0603]
R208  220  [CR1608-0603]
R209  10K  [CR1608-0603]
R212  1K  [CR1608-0603]
R213  5.23k  [CR1608-0603]
R214  5.23k  [CR1608-0603]
R233  220  [CR1608-0603]
R240  10K  [CR1608-0603]
R245  5.23k  [CR1608-0603]
R246  100  [CR1005-0402]
R255  5.23k  [CR1608-0603]
R256  100  [CR1005-0402]
R267  10K  [CR1608-0603]
R268  220  [CR1608-0603]
R269  1K  [CR0603-0201]
R270  1K  [CR0603-0201]
R272  1K  [CR0603-0201]
R295  15K  [CR1608-0603]
R297  1K  [CR0603-0201]
R303  59K  [CR1608-0603]
R304  1K  [CR1608-0603]
R308  220  [CR1608-0603]
R320  220  [CR1608-0603]
R321  220  [CR1608-0603]
R322  220  [CR1608-0603]
R323  220  [CR1608-0603]
R325  1K  [CR1608-0603]
R332  220  [CR1608-0603]
R333  220  [CR1608-0603]
R334  220  [CR1608-0603]
R346  3K  [CR1005-0402]
R347  30K  [CR1005-0402]
R352  1k  [CR1608-0603]
R353  49.9  [CR1005-0402]
R354  49.9  [CR1005-0402]
TP9  Testpoint  [TP1-RED]  (value not drawn)
U68  SN74LVC4T245  [TSSOP16]
U69  OP284FS  [SO-8_N]  (parts A,B of 2)
U71  ADG706BRU  [ADI-RU-28_M]
U72  INA333AIDGKR  [DGK0008A_N]
U73  INA333AIDGKR  [DGK0008A_N]
U76  OP284FS  [SO-8_N]  (parts A,B of 2)
U78  INA333AIDGKR  [DGK0008A_N]
U92  INA333AIDGKR  [DGK0008A_N]
U94  OP284FS  [SO-8_N]  (parts A,B of 2)
U97  REF3012AIDBZT  [DBZ0003A_L]
W3  NL  [NETTIE1_SMDTOP]  (value not drawn)  (net tie, no BOM)

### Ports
SENSE (harness SENSE), XADC (harness XADC)

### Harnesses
XADC: XADC_REF_P, XADC_V_N, XADC_V_P, XMUX[3..0], XADC_REF_N
SENSE: SENS_33_P, SENS_33_N, SENS_25_P, SENS_25_N, SENS_18_P, SENS_18_N, SENS_10_P, SENS_10_N, SENS_120x_P, SENS_120x_N, SENS_120b_P, SENS_120b_N, SENS_DVDD1V8, SENS_DVDD5V0, SENS_AVDD1V8, SENS_+15, SENS_-15, SENS_AVTT, SENS_AVCC, SENS_-15_N, SENS_-15_P, SENS_AVDD5V0

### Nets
12V: C110.1 R303.1 U94.8(V+)
+15V: C63.2 R202.1 U76.8(V+)
-15V: C67.2 FR7.1 R207.2 R212.1 U76.4(V-) ; port SENSE.SENS_-15_P  [also labelled SENS_-15_P]
AGND: C63.1 C67.1 C145.1 U76.5(IN+)
AVCC1V8: C155.1 FR9.1
GND: C110.2 C155.2 FR10.1 R295.1 U94.4(V-)
SENS_10_N: U92.2(VIN-) ; port SENSE.SENS_10_N  [project net VCC1V0]
SENS_18_N: U78.2(VIN-) ; port SENSE.SENS_18_N  [project net VCC1V8]
VCC: C116.1 C117.1 C143.1 FR3.1 R197.1 R209.1 R240.1 R267.1 U72.2(VIN-) U73.7(V+) U78.7(V+) U92.7(V+) ; port SENSE.SENS_33_N  [also labelled SENS_33_N]
VCC2: C57.1 C59.2 C144.1 FR3.2 TP9.1 U68.1(VA) U69.8(V+) U71.1(VDD) U71.18(EN)
VCC2V5: FR2.2 U73.2(VIN-) ; port SENSE.SENS_25_N  [also labelled SENS_25_N]
VREG: FR4.1
VREG2: C142.1 FR4.2 U72.7(V+)
XADCGND: C57.2 C58.1 C59.1 C116.2 C117.2 C142.2 C143.2 C144.2 C154.2 C158.2 C163.2 FR10.2 R177.1 R198.2 R203.2 R205.2 R206.2 R246.2 R256.2 R304.2 R352.1 U68.2(1DIR) U68.3(2DIR) U68.8(GND) U68.9(GND) U68.14(2~{OE}) U68.15(1~{OE}) U69.3(IN+) U69.4(V-) U71.12(GND) U71.27(VSS) U72.4(V-) U73.4(V-) U78.4(V-) U92.4(V-) U97.3(GND) W3.1
XADCVCC: C154.1 C158.1 FR9.2 U97.1(IN)
SENS1: R199.2 U71.19(S1)
SENS2: R200.2 U71.20(S2)
SENS3: R201.2 U71.21(S3)
SENS4: R332.2 U71.22(S4)
SENS5: R333.2 U71.23(S5)
SENS6: R334.2 U71.24(S6)
SENS7: R320.2 U71.25(S7)
SENS8: R323.2 U71.26(S8)
SENS9: R208.2 U71.11(S9)
SENS10: R196.2 U71.10(S10)
SENS11: R321.2 U71.9(S11)
SENS12: R233.2 U71.8(S12)
SENS13: R308.2 U71.7(S13)
SENS14: Q3.3(C) Q4.3(C) R295.2 U71.6(S14)
SENS15: R268.2 U71.5(S15)
SENS16: R322.2 U71.4(S16)
SENS_10_P: U92.3(VIN+) ; port SENSE.SENS_10_P  [project net SENSE.SENS_10_P]
SENS_18_P: U78.3(VIN+) ; port SENSE.SENS_18_P  [project net SENSE.SENS_18_P]
SENS_25_P: U73.3(VIN+) ; port SENSE.SENS_25_P  [project net SENSE.SENS_25_P]
SENS_33_P: U72.3(VIN+) ; port SENSE.SENS_33_P  [project net SENSE.SENS_33_P]
SENS_120b_N: R269.2 ; port SENSE.SENS_120b_N  [project net SENSE.SENS_120b_N]
SENS_120b_P: R272.2 ; port SENSE.SENS_120b_P  [project net SENSE.SENS_120b_P]
SENS_120x_N: R270.1 ; port SENSE.SENS_120x_N  [project net SENSE.SENS_120x_N]
SENS_120x_P: R297.1 ; port SENSE.SENS_120x_P  [project net SENSE.SENS_120x_P]
SENS_+15: R332.1 ; port SENSE.SENS_+15  [project net SENSE.SENS_+15]
SENS_-15_N: R325.1 ; port SENSE.SENS_-15_N  [project net SENSE.SENS_-15_N]
SENS_AVCC: R334.1 ; port SENSE.SENS_AVCC  [project net SENSE.SENS_AVCC]
SENS_AVDD1V8: R321.1 ; port SENSE.SENS_AVDD1V8  [project net SENSE.SENS_AVDD1V8]
SENS_AVDD5V0: R322.1 ; port SENSE.SENS_AVDD5V0  [project net SENSE.SENS_AVDD5V0]
SENS_AVTT: R333.1 ; port SENSE.SENS_AVTT  [project net SENSE.SENS_AVTT]
SENS_DVDD1V8: R320.1 ; port SENSE.SENS_DVDD1V8  [project net SENSE.SENS_DVDD1V8]
SENS_DVDD5V0: R323.1 ; port SENSE.SENS_DVDD5V0  [project net SENSE.SENS_DVDD5V0]
XADC_N: C151.2 C204.1 R354.2 ; port XADC.XADC_V_N
XADC_P: C151.1 C204.2 R353.2 ; port XADC.XADC_V_P
XADC_REF_N: W3.2 ; port XADC.XADC_REF_N
XADC_REF_P: C163.1 R204.1 U97.2(OUT) ; port XADC.XADC_REF_P
XMUX0: U68.12(1B2)
XMUX1: U68.11(2B1)
XMUX2: U68.10(2B2)
XMUX3: U68.13(1B1)
NetC58_2: C58.2 FR2.1 U68.16(VB)
NetC62_1: C62.1 R189.2 R354.1 U69.1(OUT)
NetC62_2: C62.2 R189.1 R192.2 R352.2 U69.2(IN-)
NetC141_1: C141.1 R200.1 R347.2 U76.7(OUT)
NetC141_2: C141.2 R346.2 R347.1 U76.6(IN-)
NetC145_2: C145.2 FR7.2 R186.1 R192.1
NetC146_1: C146.1 R187.2 R353.1 U69.7(OUT)
NetC146_2: C146.2 R177.2 R186.2 R187.1 U69.6(IN-)
NetQ3_1: Q3.1(B) U94.1(OUT)
NetQ3_2: Q3.2(E) R272.1 U94.2(IN-)
NetQ4_1: Q4.1(B) U94.7(OUT)
NetQ4_2: Q4.2(E) R297.2 U94.6(IN-)
NetQ5_1: Q5.1(B) U76.1(OUT)
NetQ5_2: Q5.2(E) R346.1
NetQ5_3: Q5.3(C) R325.2 U76.3(IN+)
NetR196_1: R196.1 U72.6(VOUT)
NetR197_2: R197.2 R205.1 U72.5(REF)
NetR198_1: R198.1 R199.1 R204.2 R207.1
NetR201_1: R201.1 R202.2 R203.1
NetR206_1: R206.1 R209.2 U73.5(REF)
NetR208_1: R208.1 U73.6(VOUT)
NetR212_2: R212.2 U76.2(IN-)
NetR213_1: R213.1 U72.8(RG)
NetR213_2: R213.2 U72.1(RG)
NetR214_1: R214.1 U73.8(RG)
NetR214_2: R214.2 U73.1(RG)
NetR233_1: R233.1 U78.6(VOUT)
NetR240_2: R240.2 R246.1 U78.5(REF)
NetR245_1: R245.1 U78.8(RG)
NetR245_2: R245.2 U78.1(RG)
NetR255_1: R255.1 U92.8(RG)
NetR255_2: R255.2 U92.1(RG)
NetR256_1: R256.1 R267.2 U92.5(REF)
NetR268_1: R268.1 U92.6(VOUT)
NetR269_1: R269.1 U94.3(IN+)
NetR270_2: R270.2 U94.5(IN+)
NetR303_2: R303.2 R304.1 R308.1
NetU68_4: U68.4(1A1) U71.14(A3)
NetU68_5: U68.5(1A2) U71.17(A0)
NetU68_6: U68.6(2A1) U71.16(A1)
NetU68_7: U68.7(2A2) U71.15(A2)
NetU69_5: U69.5(IN+) U71.28(D)

Not connected (* = marked no-connect by the designer): U71 2(NC)* 3(NC)* 13(NC)*

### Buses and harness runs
bus XMUX[3..0]

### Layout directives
differential pair: XADC_N, XADC_P

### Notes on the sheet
- 12.5mOhm sense R
  2A range
  Gain 200 V/V
- INA210 configuration
  VCC = VCC2 = 3.3V
  Vout = (I x 10mohm) * 200
  I = Vout / (200 * 10mohm)
- Voltage Legend:
  SW+2V5 = 2.5V from switcher
  SW+6V = 6V from switcher
  ADC Power
  AVDD1V8 = 1.8V ADC apwr
  DVDD1V8 = 1.8V ADC dpwr
  AVDD5V0 = 5V ADC apwr
  DVDD5V0 = 5V ADC dpwr
  Phase Power:
  DVDD5V0 = > P1_5V0
  DVDD5V0 = > P2_5V0
  FPGA Power:
  AVCC1V8 = XADCVCC
  VCC3V3 = VCC
  VCC2V5 = FPGA 2.5V dpwr LVDS Power
  VCC1V8 = VDD = VCCAUX
  VCC1V0 = VCCINT = VCCBRAM
  PCIe
  AVTT = 1.2V
  AVCC = 1.0V
- 10mOhm sense R
  1A max
  Sensing gain 1Ohm

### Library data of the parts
C57 C145 = ChipCap: C0402 1.0u; Part Number: C0402C105K4PACTU
C58 C59 C110 C116 C117 C141-C144 C158 C163 = ChipCap: C0402 100n; Part Number: CL05B104KA5NNNC
C62 C146 = ChipCap: C0402 100p; Part Number: KGM05ACG1H101JH
C63 C67 = ChipCap: C0603 1.0u; Part Number: CL10B105KA8NNNC
C151 = ChipCap: C0402 NL
C154 C155 = ChipCap: C0805 10u; Part Number: CL21A106KAYNNNG
C204 = CMP-2010-00306-2: C0201 NL
FR2-FR4 FR7 FR9 FR10 = BLM31PG121SN1: ferrite bead, 120Ohm at 100MHz, 1206; Part Number: BLM31PG121SN1L
LOGO4#1 = LIGO_logo
Q3-Q5 = CMP-1048-00670-1: General Purpose Transistor, PNP Silicon, 3-Pin SOT-23, Pb-Free, Tape and Reel
R177 R203 R212 R304 R325 R352 = ChipRes1: R0603 1.0k; Part Number: RR0816P-102-D
R186 R192 = ChipRes1: R0402 200k; Part Number: MCS04020D2003BE000
R187 R189 = ChipRes1: R0402 2k; Part Number: ERA-2AEB202X
R196 R199-R201 R208 R233 R268 R308 R320-R323 R332-R334 = ChipRes1: R0603 220; Part Number: ERA3AEB221V
R197 R209 R240 R267 = ChipRes1: R0603 10k; Part Number: ERA-3ARB103V
R198 = ChipRes1: R0603 1.37k; Part Number: ERA-3AEB1371V
R202 R207 R303 = ChipRes1: R0603 59k; Part Number: ERA-3AEB5902V
R204 = ChipRes1: R0603 3.7k; Part Number: RN73R1JTTD3701B25
R205 R206 R246 R256 = ChipRes1: R0402 100; Part Number: TNPW0402100RBEED
R213 R214 R245 R255 = ChipRes1: R0603 5.23k; Part Number: ERA-3AEB5231V
R269 R270 R272 R297 = ChipRes1: R0201 1k; Part Number: ERA-1AEB102C
R295 = ChipRes1: R0603 15k; Part Number: ERA-3ARB153V
R346 = ChipRes1: R0402 3k
R347 = ChipRes1: R0402 30k; Part Number: ERA-2AEB303X
R353 R354 = ChipRes1: R0402 49.9; Part Number: ERA-2AEB49R9X
TP9 = TP_POSITIVE: Testpoint, red; Part Number: Keystone / 5000
U68 = SN74LVC4T245: Quad-Bit Dual Supply Transceiver; Part Number: SN74AVC4T245PWR
U69 U76 U94 = OP284FS: Precision Rail-to-Rail Input and Output Operational Amplifier; Part Number: OP284FSZ-REEL7
U71 = CMP-0798-00217-1: 1.8 to 5.5 V / 2.5 V, CMOS Low-Voltage 2.5 Ohm, 16-Channel Multiplexer, -40 to 85 degC, 28-pin SOP (RU-28), Tube; Part Number: ADG706BRUZ-REEL7
U72 U73 U78 U92 = CMP-0944-00088-2: Low Power, Precision Instrumentation Amplifier, -40 to 125 degC, 8-pin SOP (DGK8), Green (RoHS & no Sb/Br)
U97 = CMP-0367-00158-2: 1.25 V, 50 ppm / degC, 50 uA Series (Bandgap) Voltage Reference, -40 to 125 degC, 3-pin SOT-23 (DBZ), Green (RoHS & no Sb/Br); Part Number: REF3012AIDBZTCT-ND
W3 = NetTie1_small

## Sheet AD32_FLASH.SchDoc: JTAG & SPI Flash
size B; Revision: C; SheetNumber: 13; SheetTotal: 17
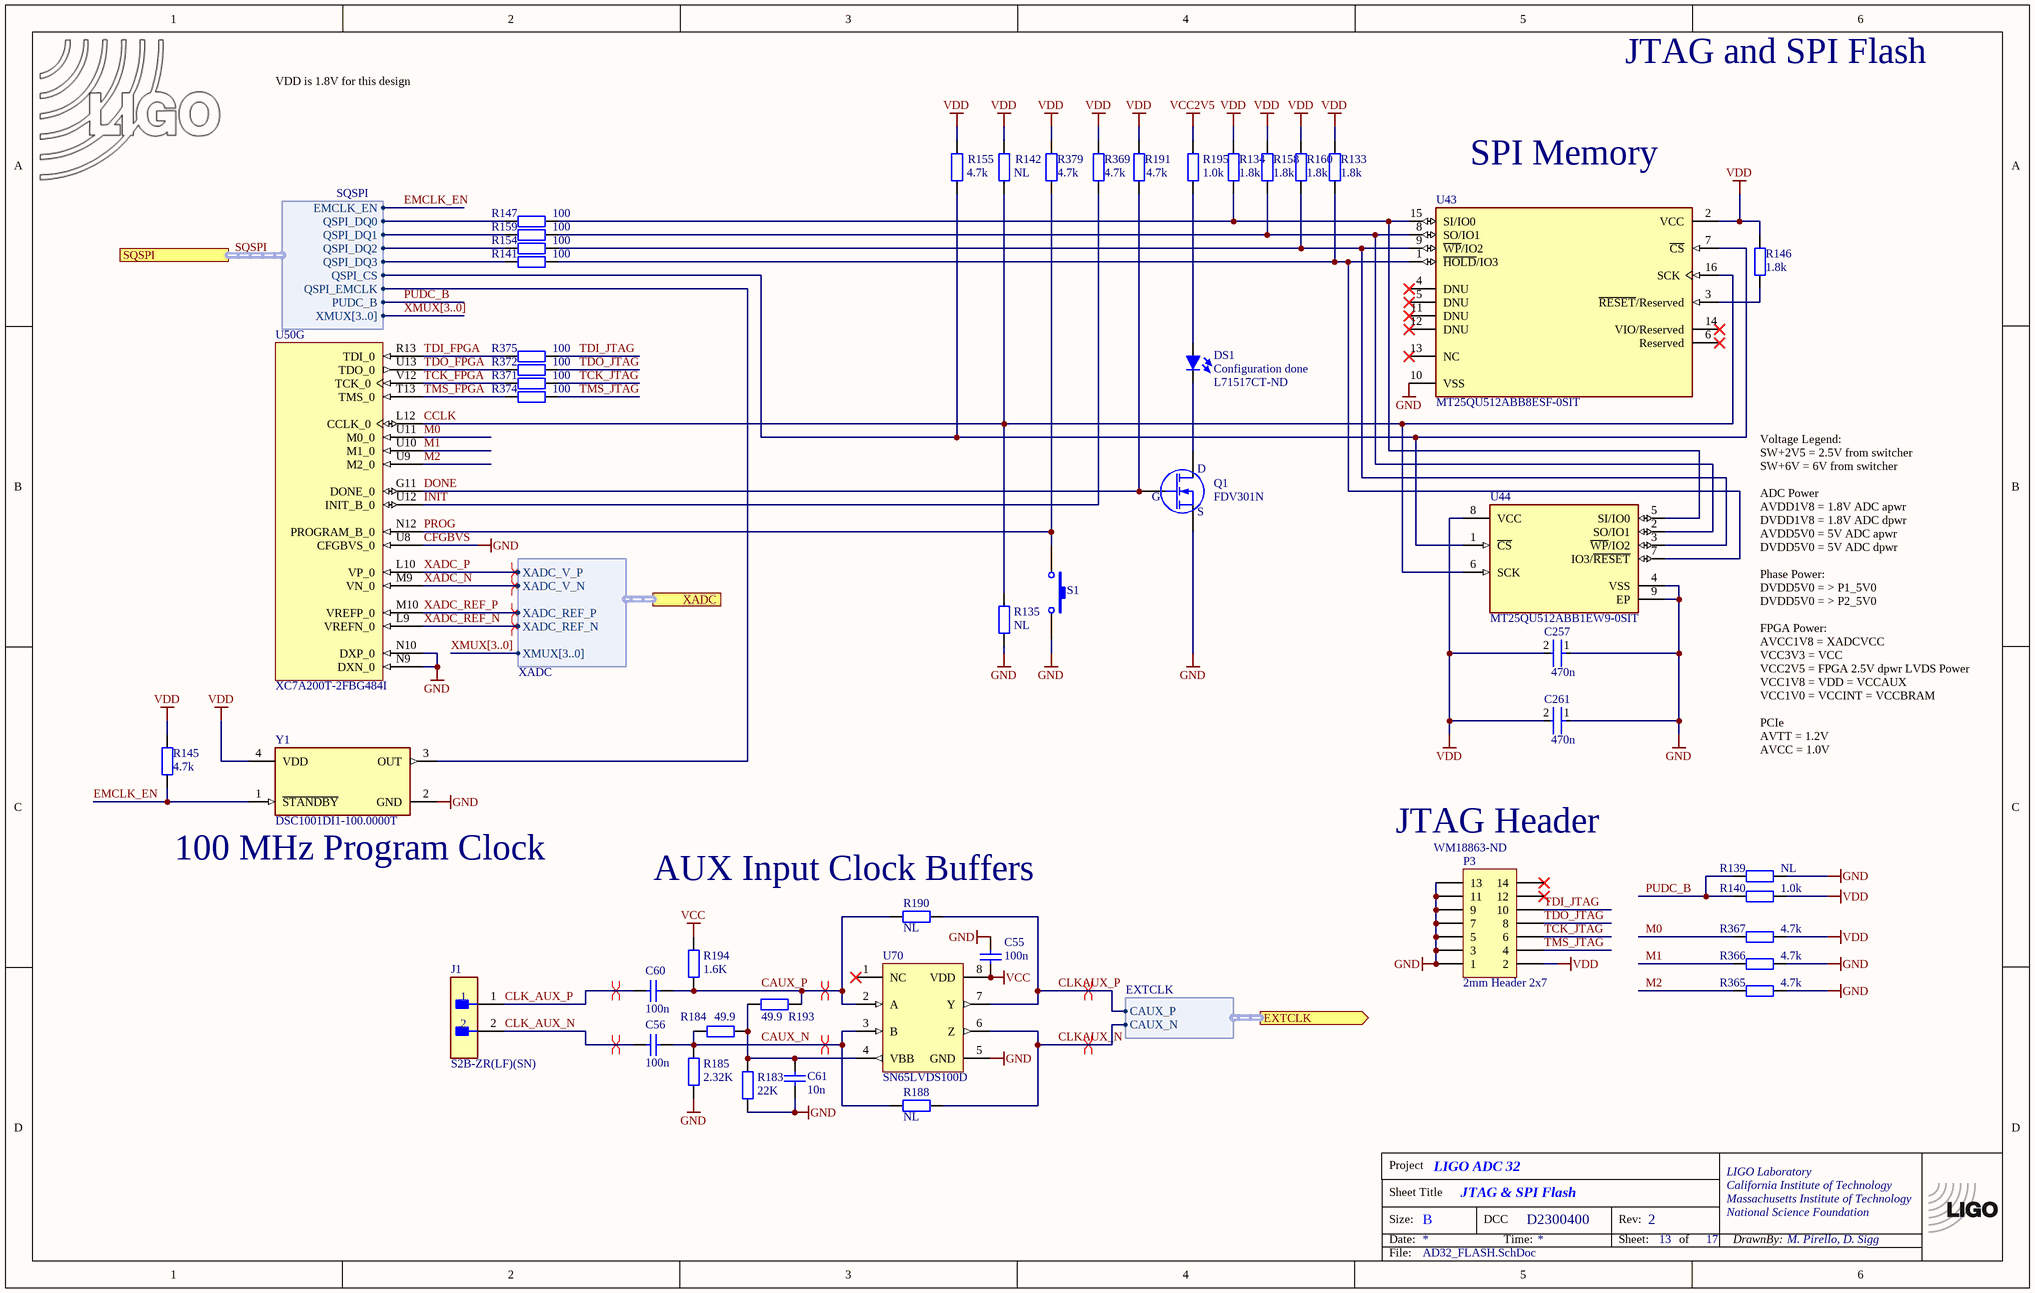
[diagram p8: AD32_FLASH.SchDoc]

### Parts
(Parts that share a designator on the sheet are numbered #1, #2 ... from top to bottom, then left to right.)
*?#5  TitleBlock  (value not drawn)  (graphical)
C55  100n  [CC2013-0805]
C56  100n  [CC1005-0402]
C60  100n  [CC1005-0402]
C61  10n  [CC1005-0402]
C257  470n  [FP-CL03-IPC_B]
C261  470n  [FP-CL03-IPC_B]
DS1  Supplier Part Number 1: L71517CT-ND  [LED-0805]  (hidden comment: LED)
J1  S2B-ZR(LF)(SN)  [FP-S2B-ZR_LF_SN-MFG]
LOGO3  LIGO logo  [LIGO_LOGO]  (value not drawn)  (graphical)
P3  2mm Header 2x7  Supplier Part Number 1: WM18863-ND  [2MM_HDR2X7_RA]
Q1  FDV301N  [SO-G3/C2.25]
R133  1.8k  [CR1005-0402]
R134  1.8k  [CR1005-0402]
R135  NL  [CR1005-0402]
R139  NL  [CR1005-0402]
R140  1.0k  [CR1005-0402]
R141  100  [CR1005-0402]
R142  NL  [CR1005-0402]
R145  4.7k  [CR1005-0402]
R146  1.8k  [CR1005-0402]
R147  100  [CR1005-0402]
R154  100  [CR1005-0402]
R155  4.7k  [CR1005-0402]
R158  1.8k  [CR1005-0402]
R159  100  [CR1005-0402]
R160  1.8k  [CR1005-0402]
R183  22K  [CR1005-0402]
R184  49.9  [CR1005-0402]
R185  2.32K  [CR1005-0402]
R188  NL  [CR1005-0402]
R190  NL  [CR1005-0402]
R191  4.7k  [CR1005-0402]
R193  49.9  [CR1005-0402]
R194  1.6K  [CR1005-0402]
R195  1.0k  [CR1005-0402]
R365  4.7k  [CR1005-0402]
R366  4.7k  [CR1005-0402]
R367  4.7k  [CR1005-0402]
R369  4.7k  [CR1005-0402]
R371  100  [CR1005-0402]
R372  100  [CR1005-0402]
R374  100  [CR1005-0402]
R375  100  [CR1005-0402]
R379  4.7k  [CR1005-0402]
S1  B3SN-3112P  [SW_SMD_6MM]  (value not drawn)
U43  MT25QU512ABB8ESF-0SIT  [FP-002-15547-MFG]
U44  MT25QU512ABB1EW9-0SIT  [FP-002-18827-MFG]  (no BOM)
U50  XC7A200T-2FBG484I  [FBG484]  (part G of 11)
U70  SN65LVDS100D  [MSOP8]
Y1  DSC1001DI1-100.0000T  [FP-CDFN2520-4LD-PL-1-MFG]

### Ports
EXTCLK (out, harness EXTCLK), SQSPI (harness SQSPI), XADC (harness XADC)

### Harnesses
SQSPI: QSPI_DQ0, QSPI_DQ1, QSPI_DQ2, QSPI_DQ3, QSPI_CS, QSPI_EMCLK, PUDC_B, XMUX[3..0], EMCLK_EN
XADC: XADC_REF_P, XADC_V_N, XADC_V_P, XMUX[3..0], XADC_REF_N
EXTCLK: CAUX_P, CAUX_N

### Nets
GND: C55.1 C61.1 C257.1 C261.1 P3.1 P3.3 P3.5 P3.7 P3.9 P3.11 P3.13 Q1.2(S) R135.2 R139.2 R183.2 R185.2 R365.2 R366.2 S1.3 S1.5 U43.10(VSS) U44.4(VSS) U44.9(EP) U50.N9(DXN_0) U50.N10(DXP_0) U50.U8(CFGBVS_0) U70.5(GND) Y1.2(GND)  [also labelled CFGBVS]
VCC: C55.2 R194.1 U70.8(VDD)
VCC2V5: R195.1
VDD: C257.2 C261.2 P3.2 R133.2 R134.2 R140.2 R142.1 R145.1 R146.2 R155.1 R158.2 R160.2 R191.2 R367.2 R369.2 R379.2 U43.2(VCC) U44.8(VCC) Y1.4(VDD)  [project net VCC1V8]
CAUX_N: C56.2 R184.2 R185.1 R188.1 U70.3(B)
CAUX_P: C60.2 R190.1 R193.1 R194.2 U70.2(A)
CCLK: R135.1 R142.2 U43.16(SCK) U44.6(SCK) U50.L12(CCLK_0)
CLK_AUX_N: C56.1 J1.2
CLK_AUX_P: C60.1 J1.1
CLKAUX_N: R188.2 U70.6(Z) ; port EXTCLK.CAUX_N  [project net EXTCLK.CAUX_N]
CLKAUX_P: R190.2 U70.7(Y) ; port EXTCLK.CAUX_P  [project net EXTCLK.CAUX_P]
DONE: Q1.1(G) R191.1 U50.G11(DONE_0)
EMCLK_EN: R145.2 Y1.1(~{STANDBY}) ; port SQSPI.EMCLK_EN  [project net SQSPI.EMCLK_EN]
INIT: R369.1 U50.U12(INIT_B_0)
M0: R367.1 U50.U11(M0_0)
M1: R366.1 U50.U10(M1_0)
M2: R365.1 U50.U9(M2_0)
PROG: R379.1 S1.1 U50.N12(PROGRAM_B_0)
PUDC_B: R139.1 R140.1 ; port SQSPI.PUDC_B  [project net SQSPI.PUDC_B]
SQSPI.QSPI_CS: R155.2 U43.7(~{CS}) U44.1(~{CS}) ; port SQSPI.QSPI_CS
SQSPI.QSPI_DQ0: R147.2 ; port SQSPI.QSPI_DQ0
SQSPI.QSPI_DQ1: R159.2 ; port SQSPI.QSPI_DQ1
SQSPI.QSPI_DQ2: R154.2 ; port SQSPI.QSPI_DQ2
SQSPI.QSPI_DQ3: R141.2 ; port SQSPI.QSPI_DQ3
SQSPI.QSPI_EMCLK: Y1.3(OUT) ; port SQSPI.QSPI_EMCLK
TCK_FPGA: R371.2 U50.V12(TCK_0)
TCK_JTAG: P3.6 R371.1
TDI_FPGA: R375.2 U50.R13(TDI_0)
TDI_JTAG: P3.10 R375.1
TDO_FPGA: R372.2 U50.U13(TDO_0)
TDO_JTAG: P3.8 R372.1
TMS_FPGA: R374.2 U50.T13(TMS_0)
TMS_JTAG: P3.4 R374.1
XADC_N: U50.M9(VN_0) ; port XADC.XADC_V_N
XADC_P: U50.L10(VP_0) ; port XADC.XADC_V_P
XADC_REF_N: U50.L9(VREFN_0) ; port XADC.XADC_REF_N
XADC_REF_P: U50.M10(VREFP_0) ; port XADC.XADC_REF_P
NetC61_2: C61.2 R183.1 R184.1 R193.2 U70.4(VBB)
NetDS1_1: DS1.1(K) Q1.3(D)
NetDS1_2: DS1.2(A) R195.2
NetR133_1: R133.1 R141.1 U43.1(~{HOLD}/IO3) U44.7(IO3/~{RESET})
NetR134_1: R134.1 R147.1 U43.15(SI/IO0) U44.5(SI/IO0)
NetR146_1: R146.1 U43.3(~{RESET}/Reserved)
NetR154_1: R154.1 R160.1 U43.9(~{WP}/IO2) U44.3(~{WP}/IO2)
NetR158_1: R158.1 R159.1 U43.8(SO/IO1) U44.2(SO/IO1)

Not connected (* = marked no-connect by the designer): P3 12* 14*; U43 4(DNU)* 5(DNU)* 6(Reserved)* 11(DNU)* 12(DNU)* 13(NC)* 14(VIO/Reserved)*; U70 1(NC)*

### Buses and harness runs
bus XMUX[3..0]
harness SQSPI = port SQSPI

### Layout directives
differential pair: CAUX_N, CAUX_P, CLK_AUX_N, CLK_AUX_P, EXTCLK.CAUX_N, EXTCLK.CAUX_P, XADC_N, XADC_P, XADC_REF_N, XADC_REF_P

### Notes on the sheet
- JTAG and SPI Flash
- VDD is 1.8V for this design
- (near U43) SPI Memory
- (near DS1) Configuration done
- (near P3) JTAG Header
- Voltage Legend:
  SW+2V5 = 2.5V from switcher
  SW+6V = 6V from switcher
  ADC Power
  AVDD1V8 = 1.8V ADC apwr
  DVDD1V8 = 1.8V ADC dpwr
  AVDD5V0 = 5V ADC apwr
  DVDD5V0 = 5V ADC dpwr
  Phase Power:
  DVDD5V0 = > P1_5V0
  DVDD5V0 = > P2_5V0
  FPGA Power:
  AVCC1V8 = XADCVCC
  VCC3V3 = VCC
  VCC2V5 = FPGA 2.5V dpwr LVDS Power
  VCC1V8 = VDD = VCCAUX
  VCC1V0 = VCCINT = VCCBRAM
  PCIe
  AVTT = 1.2V
  AVCC = 1.0V
- (near Y1) 100 MHz Program Clock
- (near R190) AUX Input Clock Buffers

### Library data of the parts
C55 = ChipCap: C0805 100n; Part Number: KGM21NR71H104KM
C56 C60 = ChipCap: C0402 100n; Part Number: CL05B104KA5NNNC
C61 = ChipCap: C0402 10n; Part Number: CC0402KRX7R9BB103
C257 C261 = CMP-2010-00306-2: C0201 470n; Part Number: CL03A474KQ3NNNC
DS1 = LED: Panel mount LED
J1 = CMP-2000-07021-2: CONN HEADER R/A 2POS 1.5MM
LOGO3 = LIGO_logo
P3 = Xilinx_JTAG_Header: Xilinx JTAG header, 7-Pin, Dual row
Q1 = FDV301N: FDV301N, Digital FET, N-channel, SOT23; Part Number: FDV301NCT-ND
R133 R134 R146 R158 R160 = ChipRes1: R0402 1.8k; Part Number: RR05P1.8KDCT-ND
R135 R139 R142 R188 R190 = ChipRes1: R0402 NL
R140 R195 = ChipRes1: R0402 1.0k; Part Number: RT0402BRD071KL
R141 R147 R154 R159 R371 R372 R374 R375 = ChipRes1: R0402 100; Part Number: TNPW0402100RBEED
R145 R155 R191 R365-R367 R369 R379 = ChipRes1: R0402 4.7k; Part Number: ERA-2AED472X
R183 = ChipRes1: R0402 22k; Part Number: ERA-2AED223X
R184 R193 = ChipRes1: R0402 49.9; Part Number: ERA-2AEB49R9X
R185 = ChipRes1: R0402 2.32k; Part Number: RT0402BRD072K32L
R194 = ChipRes1: R0402 1.6k; Part Number: ERA-2AEB162X
S1 = B3SN-3112P: Switch, SMD, 6mm; Part Number: SW262CT-ND
U43 = CMP-12948-000005-1: IC FLASH 128M SPI 133MHZ 16SOIC
U44 = CMP-12948-000008-1: IC FLASH 256M SPI 133MHZ 8WSON
U50 = CMP-0364-00012-3: as U50 on sheet FPGA_ARTIX7
U70 = SN65LVDS100: DIFF TRANSLATOR; Part Number: 296-39184-1-ND
Y1 = CMP-06255-000005-1: MEMS OSC XO 100.0000MHZ CMOS SMD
